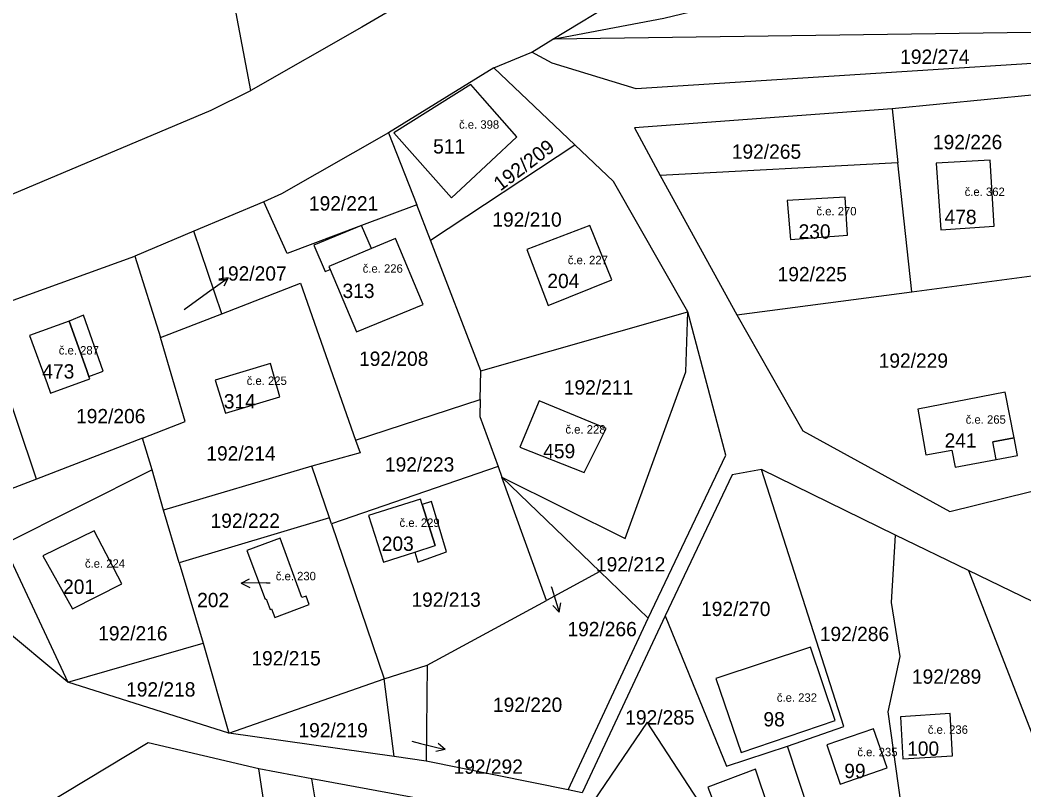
# Model space of a CAD drawing. Extents: x -887272 to -880188, y -1026687 to -1021896.
# Drawn here: x -882201.9 to -882082.9, y -1024103.2 to -1024011.9 of the extents above; entities that cross this region are included whole.
import ezdxf

# ---------------------------------------------------------------- set-up
doc = ezdxf.new("R2010")
doc.units = 0
for name, color, linetype in [('Definiční body', 7, 'Continuous'), ('Hranice parcel', 7, 'Continuous'), ('Parcelní čísla', 7, 'Continuous'), ('Polygon budovy', 7, 'Continuous'), ('Pop  PČ popisy', 7, 'Continuous'), ('Vnitřní kresba', 7, 'Continuous')]:
    doc.layers.add(name, color=color, linetype=linetype)

msp = doc.modelspace()

# ---------------------------------------------------------------- linework, layer by layer
at = {"layer": 'Hranice parcel'}
for p, q in [((-882138.72, -1024014.17), (-882123.98, -1024005.14)), ((-882141.19, -1024015.69), (-882138.72, -1024014.17)), ((-882145.71, -1024017.54), (-882141.19, -1024015.69)), ((-882145.71, -1024017.54), (-882158.18, -1024025.27)), ((-882136.1, -1024026.69), (-882145.71, -1024017.54)), ((-882081.54, -1024020.75), (-882098.51, -1024022.43)), ((-882098.51, -1024022.43), (-882097.82, -1024028.81)), ((-882158.18, -1024025.27), (-882154.84, -1024033.81)), ((-882153.2, -1024037.99), (-882136.1, -1024026.69)), ((-882097.82, -1024028.81), (-882125.97, -1024030.31)), ((-882096.15, -1024044.11), (-882097.82, -1024028.81)), ((-882125.97, -1024030.31), (-882116.91, -1024046.86)), ((-882172.96, -1024033.47), (-882181.25, -1024036.95)), ((-882170.21, -1024039.58), (-882172.96, -1024033.47)), ((-882153.2, -1024037.99), (-882154.84, -1024033.81)), ((-882181.25, -1024036.95), (-882188.26, -1024039.89)), ((-882177.94, -1024046.73), (-882181.25, -1024036.95)), ((-882147.26, -1024053.51), (-882153.2, -1024037.99)), ((-882206.58, -1024046.52), (-882188.26, -1024039.89)), ((-882188.26, -1024039.89), (-882185.22, -1024049.56)), ((-882096.15, -1024044.11), (-882078.8, -1024041.81)), ((-882116.91, -1024046.86), (-882096.15, -1024044.11)), ((-882199.93, -1024066.33), (-882206.58, -1024046.52)), ((-882185.22, -1024049.56), (-882177.94, -1024046.73)), ((-882147.26, -1024053.51), (-882122.72, -1024046.51)), ((-882147.32, -1024056.9), (-882147.26, -1024053.51)), ((-882162.09, -1024061.72), (-882147.32, -1024056.9)), ((-882187.35, -1024061.47), (-882199.93, -1024066.33)), ((-882186.22, -1024065.24), (-882187.35, -1024061.47)), ((-882184.87, -1024070.04), (-882186.22, -1024065.24)), ((-882167.27, -1024064.79), (-882184.87, -1024070.04)), ((-882165.18, -1024070.94), (-882167.27, -1024064.79)), ((-882145.21, -1024064.85), (-882164.94, -1024071.65)), ((-882145.21, -1024064.85), (-882144.76, -1024066.09)), ((-882098.08, -1024072.99), (-882113.98, -1024065.19)), ((-882199.93, -1024066.33), (-882217.07, -1024073.03)), ((-882144.76, -1024066.09), (-882133.16, -1024077.29)), ((-882139.48, -1024080.73), (-882144.76, -1024066.09)), ((-882183, -1024076.28), (-882184.87, -1024070.04)), ((-882165.18, -1024070.94), (-882183, -1024076.28)), ((-882164.94, -1024071.65), (-882165.18, -1024070.94)), ((-882164.94, -1024071.65), (-882158.69, -1024090.04)), ((-882089.45, -1024077.18), (-882098.08, -1024072.99)), ((-882196.2, -1024090.44), (-882217.07, -1024073.03)), ((-882183, -1024076.28), (-882180.16, -1024085.79)), ((-882133.16, -1024077.29), (-882139.48, -1024080.73)), ((-882133.16, -1024077.29), (-882127.41, -1024082.85)), ((-882089.45, -1024077.18), (-882079.4, -1024103.11)), ((-882153.6, -1024088.41), (-882139.48, -1024080.73)), ((-882136.89, -1024103.2), (-882127.41, -1024082.85)), ((-882125.39, -1024082.57), (-882135.22, -1024103.54)), ((-882196.2, -1024090.44), (-882180.16, -1024085.79)), ((-882180.16, -1024085.79), (-882177.1, -1024096.46)), ((-882158.69, -1024090.04), (-882153.6, -1024088.41)), ((-882153.6, -1024088.41), (-882153.74, -1024099.78)), ((-882177.1, -1024096.46), (-882196.2, -1024090.44)), ((-882177.1, -1024096.46), (-882158.69, -1024090.04)), ((-882157.5, -1024099.25), (-882158.69, -1024090.04)), ((-882157.5, -1024099.25), (-882177.1, -1024096.46)), ((-882106.8, -1024110.48), (-882110.89, -1024098.01)), ((-882153.74, -1024099.78), (-882157.5, -1024099.25)), ((-882136.89, -1024103.2), (-882153.74, -1024099.78)), ((-882171.6, -1024113.68), (-882173.55, -1024100.7)), ((-882167.27, -1024101.87), (-882173.55, -1024100.7)), ((-882162.36, -1024132.25), (-882167.27, -1024101.87)), ((-882135.22, -1024103.54), (-882136.89, -1024103.2))]:
    msp.add_line(p, q, dxfattribs=at)
for points in [[(-882174.49, -1024020.26), (-882208.33, -1023841.98), (-882227.5, -1023772.45), (-882213.17, -1023769.2), (-882180.99, -1023853.37), (-882162.93, -1023941.67)], [(-882138.72, -1024014.17), (-882125.55, -1024011.67), (-882085.96, -1024002.08), (-882063.17, -1024001.87), (-882034.49, -1024011.62), (-882004.55, -1024020.66), (-881996.26, -1024020.9)], [(-882148.29, -1024005.05), (-882161.34, -1024012.72), (-882174.49, -1024020.26)], [(-881966.06, -1024029.4), (-882045.19, -1024012.84), (-882138.72, -1024014.17)], [(-881990.45, -1024031.46), (-882004.32, -1024026.5), (-882043.3, -1024015.89), (-882047.34, -1024014.83), (-882128.82, -1024020.06), (-882138.81, -1024017.01), (-882141.19, -1024015.69)], [(-882340.1, -1024040.68), (-882291.8, -1024041.02), (-882266.44, -1024041.52), (-882231.92, -1024039.84), (-882208.92, -1024035.12), (-882179.22, -1024022.58), (-882174.49, -1024020.26)], [(-882147.04, -1024021.13), (-882148.45, -1024019.53), (-882157.57, -1024025.28), (-882150.72, -1024032.97)], [(-882150.72, -1024032.97), (-882149.08, -1024031.43), (-882142.96, -1024025.76), (-882147.04, -1024021.13)], [(-882098.51, -1024022.43), (-882129.05, -1024024.69), (-882125.97, -1024030.31)], [(-882158.18, -1024025.27), (-882170.87, -1024032.49), (-882172.96, -1024033.47)], [(-882122.72, -1024046.51), (-882131.54, -1024031.03), (-882136.1, -1024026.69)], [(-882086.4, -1024036.35), (-882086.89, -1024028.52), (-882093.28, -1024028.88), (-882092.71, -1024036.76), (-882086.4, -1024036.35)], [(-882103.78, -1024037.42), (-882104.08, -1024032.9), (-882110.92, -1024033.31), (-882110.54, -1024037.9), (-882103.78, -1024037.42)], [(-882154.84, -1024033.81), (-882161.39, -1024036.27), (-882170.21, -1024039.58)], [(-882160.2, -1024038.98), (-882161.39, -1024036.27), (-882167.05, -1024038.59)], [(-882141.79, -1024039.12), (-882139.27, -1024045.73), (-882131.7, -1024042.7), (-882134.31, -1024036.26), (-882141.79, -1024039.12)], [(-882167.05, -1024038.59), (-882165.7, -1024041.71), (-882165.11, -1024041.46), (-882161.99, -1024048.88), (-882154.07, -1024045.61), (-882157.36, -1024037.79), (-882160.2, -1024038.98)], [(-882177.94, -1024046.73), (-882168.62, -1024043.1), (-882162.09, -1024061.72)], [(-882144.76, -1024066.09), (-882130.14, -1024073.37), (-882122.96, -1024053.6), (-882122.72, -1024046.51)], [(-882127.41, -1024082.85), (-882118.21, -1024063.51), (-882122.72, -1024046.51)], [(-882198.66, -1024055), (-882198.26, -1024056.13), (-882193.59, -1024054.46), (-882193.69, -1024054.18), (-882191.99, -1024053.54), (-882194.34, -1024046.88), (-882196.04, -1024047.62), (-882200.75, -1024049.31), (-882198.66, -1024055)], [(-882116.91, -1024046.86), (-882109.08, -1024060.61), (-882091.67, -1024070.17), (-882075.8, -1024066.27)], [(-882187.35, -1024061.47), (-882182.29, -1024059.51), (-882185.22, -1024049.56)], [(-882172.16, -1024052.64), (-882178.74, -1024054.62), (-882177.51, -1024058.53), (-882171.05, -1024056.59), (-882172.16, -1024052.64)], [(-882091.02, -1024064.92), (-882086.18, -1024064.01), (-882083.62, -1024063.53), (-882084.03, -1024061.44), (-882085.09, -1024056.03), (-882095.44, -1024058.05), (-882094.51, -1024063.45), (-882091.4, -1024062.91), (-882091.02, -1024064.92)], [(-882147.32, -1024056.9), (-882147.35, -1024058.92), (-882145.21, -1024064.85)], [(-882132.4, -1024060.34), (-882140.32, -1024057.06), (-882142.64, -1024062.56), (-882134.98, -1024065.56), (-882132.4, -1024060.34)], [(-882162.09, -1024061.72), (-882161.56, -1024063.23), (-882167.27, -1024064.79)], [(-882186.22, -1024065.24), (-882203.83, -1024074.1), (-882196.2, -1024090.44)], [(-882113.98, -1024065.19), (-882117.47, -1024065.82), (-882125.39, -1024082.57)], [(-882110.89, -1024098.01), (-882104.21, -1024095.67), (-882113.98, -1024065.19)], [(-882154.4, -1024068.72), (-882160.55, -1024070.67), (-882158.8, -1024076.18), (-882155.08, -1024075), (-882154.7, -1024076.19), (-882151.32, -1024074.97), (-882153.11, -1024068.99), (-882154.2, -1024069.34), (-882154.4, -1024068.72)], [(-882189.78, -1024078.76), (-882193.08, -1024072.46), (-882199.16, -1024075.44), (-882195.66, -1024081.74), (-882189.78, -1024078.76)], [(-882097.11, -1024107.19), (-882098.95, -1024093.95), (-882097.56, -1024087.36), (-882098.57, -1024080.99), (-882098.08, -1024072.99)], [(-882171.68, -1024082.77), (-882167.58, -1024081.22), (-882167.94, -1024080.21), (-882168.46, -1024080.4), (-882171.04, -1024073.33), (-882174.98, -1024074.82), (-882172.81, -1024080.57), (-882172.7, -1024080.53), (-882172.22, -1024081.79), (-882172.07, -1024081.73), (-882171.68, -1024082.77)], [(-882060.37, -1024098.33), (-882059.72, -1024094.32), (-882061.57, -1024090.71), (-882089.45, -1024077.18)], [(-882125.39, -1024082.57), (-882118.13, -1024100.39), (-882110.89, -1024098.01)], [(-882119.38, -1024089.98), (-882116.4, -1024098.76), (-882105.23, -1024094.97), (-882108.18, -1024086.28), (-882119.38, -1024089.98)], [(-882091.34, -1024099.18), (-882091.62, -1024094.14), (-882097.51, -1024094.52), (-882097.21, -1024099.52), (-882091.34, -1024099.18)], [(-882115.87, -1024113.05), (-882127.53, -1024095.15), (-882133.96, -1024104.67), (-882136.92, -1024107.16)], [(-882104.64, -1024102.51), (-882099.09, -1024100.58), (-882100.71, -1024095.94), (-882106.24, -1024097.84), (-882104.64, -1024102.51)], [(-882173.55, -1024100.7), (-882186.69, -1024097.6), (-882198.92, -1024105.01)], [(-882120.33, -1024102.86), (-882118.57, -1024107.51), (-882113.1, -1024105.46), (-882114.69, -1024100.73), (-882120.33, -1024102.86)], [(-882146.33, -1024121.21), (-882152.94, -1024104.55), (-882167.27, -1024101.87)]]:
    msp.add_lwpolyline(points, dxfattribs=at)
at = {"layer": 'Polygon budovy'}
for points in [[(-882147.04, -1024021.13), (-882148.45, -1024019.53), (-882157.57, -1024025.28), (-882150.72, -1024032.97), (-882149.08, -1024031.43), (-882142.96, -1024025.76)], [(-882093.28, -1024028.88), (-882092.71, -1024036.76), (-882086.4, -1024036.35), (-882086.89, -1024028.52)], [(-882104.08, -1024032.9), (-882110.92, -1024033.31), (-882110.54, -1024037.9), (-882103.78, -1024037.42)], [(-882139.27, -1024045.73), (-882131.7, -1024042.7), (-882134.31, -1024036.26), (-882141.79, -1024039.12)], [(-882157.36, -1024037.79), (-882160.2, -1024038.98), (-882165.26, -1024041.11), (-882165.11, -1024041.46), (-882161.99, -1024048.88), (-882154.07, -1024045.61)], [(-882196.04, -1024047.62), (-882200.75, -1024049.31), (-882198.66, -1024055), (-882198.26, -1024056.13), (-882193.59, -1024054.46), (-882193.69, -1024054.18), (-882193.98, -1024053.35)], [(-882178.74, -1024054.62), (-882177.51, -1024058.53), (-882171.05, -1024056.59), (-882172.16, -1024052.64)], [(-882084.03, -1024061.44), (-882085.09, -1024056.03), (-882095.44, -1024058.05), (-882094.51, -1024063.45), (-882091.4, -1024062.91), (-882091.02, -1024064.92), (-882086.18, -1024064.01), (-882086.57, -1024061.93)], [(-882140.32, -1024057.06), (-882142.64, -1024062.56), (-882134.98, -1024065.56), (-882132.4, -1024060.34)], [(-882158.8, -1024076.18), (-882155.08, -1024075), (-882152.65, -1024074.23), (-882154.2, -1024069.34), (-882154.4, -1024068.72), (-882160.55, -1024070.67)], [(-882193.08, -1024072.46), (-882199.16, -1024075.44), (-882195.66, -1024081.74), (-882189.78, -1024078.76)], [(-882171.04, -1024073.33), (-882174.98, -1024074.82), (-882172.81, -1024080.57), (-882172.7, -1024080.53), (-882172.22, -1024081.79), (-882172.07, -1024081.73), (-882171.68, -1024082.77), (-882167.58, -1024081.22), (-882167.94, -1024080.21), (-882168.46, -1024080.4)], [(-882116.4, -1024098.76), (-882105.23, -1024094.97), (-882108.18, -1024086.28), (-882119.38, -1024089.98)], [(-882091.62, -1024094.14), (-882097.51, -1024094.52), (-882097.21, -1024099.52), (-882091.34, -1024099.18)], [(-882106.24, -1024097.84), (-882104.64, -1024102.51), (-882099.09, -1024100.58), (-882100.71, -1024095.94)], [(-882120.33, -1024102.86), (-882118.57, -1024107.51), (-882113.1, -1024105.46), (-882114.69, -1024100.73)]]:
    msp.add_lwpolyline(points, close=True, dxfattribs=at)
at = {"layer": 'Pop  PČ popisy'}
for p, q in [((-882179.63, -1024044.21), (-882177.2, -1024042.45)), ((-882177.2, -1024042.45), (-882178.31, -1024042.63)), ((-882177.2, -1024042.45), (-882177.72, -1024043.44)), ((-882182.42, -1024046.22), (-882179.63, -1024044.21)), ((-882175.64, -1024078.69), (-882174.65, -1024078.17)), ((-882172.64, -1024078.64), (-882175.64, -1024078.69)), ((-882175.64, -1024078.69), (-882174.63, -1024079.18)), ((-882172.64, -1024078.64), (-882172.22, -1024078.64)), ((-882138.89, -1024079.08), (-882138.84, -1024079.26)), ((-882138.84, -1024079.26), (-882137.96, -1024082.13)), ((-882137.96, -1024082.13), (-882138.73, -1024081.32)), ((-882137.96, -1024082.13), (-882137.78, -1024081.03)), ((-882155.43, -1024097.42), (-882154.38, -1024097.69)), ((-882154.38, -1024097.69), (-882151.47, -1024098.42)), ((-882151.47, -1024098.42), (-882152.32, -1024097.69)), ((-882151.47, -1024098.42), (-882152.56, -1024098.66))]:
    msp.add_line(p, q, dxfattribs=at)
at = {"layer": 'Vnitřní kresba'}
for p, q in [((-882160.2, -1024038.98), (-882165.26, -1024041.11)), ((-882165.26, -1024041.11), (-882165.11, -1024041.46)), ((-882196.04, -1024047.62), (-882193.98, -1024053.35)), ((-882193.98, -1024053.35), (-882193.69, -1024054.18)), ((-882084.03, -1024061.44), (-882086.57, -1024061.93)), ((-882086.18, -1024064.01), (-882086.57, -1024061.93)), ((-882154.2, -1024069.34), (-882152.65, -1024074.23)), ((-882155.08, -1024075), (-882152.65, -1024074.23))]:
    msp.add_line(p, q, dxfattribs=at)

# ---------------------------------------------------------------- texts
at = {"layer": 'Definiční body'}
for s, p in [('č.e. 398', (-882149.83, -1024024.78)), ('č.e. 362', (-882089.9, -1024032.76)), ('č.e. 270', (-882107.47, -1024035.06)), ('č.e. 226', (-882161.25, -1024041.86)), ('č.e. 227', (-882136.94, -1024040.85)), ('č.e. 287', (-882197.27, -1024051.56)), ('č.e. 225', (-882175, -1024055.17)), ('č.e. 265', (-882089.78, -1024059.77)), ('č.e. 228', (-882137.22, -1024060.94)), ('č.e. 229', (-882156.88, -1024072.01)), ('č.e. 224', (-882194.17, -1024076.85)), ('č.e. 230', (-882171.55, -1024078.34)), ('č.e. 232', (-882112.16, -1024092.75)), ('č.e. 236', (-882094.27, -1024096.55)), ('č.e. 235', (-882102.62, -1024099.21))]:
    msp.add_text(s, height=1, dxfattribs=at).set_placement(p)
at = {"layer": 'Parcelní čísla'}
for s, p in [('192/274', (-882097.54, -1024017.09)), ('192/226', (-882093.66, -1024027.21)), ('511', (-882152.9, -1024027.72)), ('192/265', (-882117.5, -1024028.34)), ('192/221', (-882167.62, -1024034.48)), ('192/210', (-882145.88, -1024036.4)), ('478', (-882092.28, -1024036.09)), ('230', (-882109.58, -1024037.82)), ('192/207', (-882178.48, -1024042.8)), ('204', (-882139.36, -1024043.68)), ('192/225', (-882112.07, -1024042.88)), ('313', (-882163.64, -1024044.86)), ('192/208', (-882161.68, -1024052.91)), ('192/229', (-882100.09, -1024053.13)), ('473', (-882199.22, -1024054.41)), ('192/211', (-882137.41, -1024056.31)), ('314', (-882177.71, -1024057.96)), ('192/206', (-882195.22, -1024059.72)), ('241', (-882092.28, -1024062.61)), ('459', (-882139.85, -1024063.87)), ('192/214', (-882179.78, -1024064.14)), ('192/223', (-882158.61, -1024065.45)), ('192/222', (-882179.28, -1024072.12)), ('203', (-882158.99, -1024074.85)), ('192/212', (-882133.6, -1024077.29)), ('201', (-882196.76, -1024079.95)), ('202', (-882180.87, -1024081.53)), ('192/213', (-882155.47, -1024081.48)), ('192/270', (-882121.14, -1024082.58)), ('192/216', (-882192.6, -1024085.48)), ('192/266', (-882136.98, -1024084.98)), ('192/286', (-882107.07, -1024085.55)), ('192/215', (-882174.44, -1024088.44)), ('192/289', (-882096.15, -1024090.61)), ('192/218', (-882189.29, -1024092.13)), ('192/220', (-882145.81, -1024093.95)), ('192/285', (-882130.13, -1024095.45)), ('98', (-882113.75, -1024095.67)), ('192/219', (-882168.86, -1024096.97)), ('100', (-882096.72, -1024099.15)), ('192/292', (-882150.48, -1024101.29)), ('99', (-882104.17, -1024101.8))]:
    msp.add_text(s, height=1.7, dxfattribs=at).set_placement(p)
msp.add_text('192/209', height=1.7, rotation=37, dxfattribs=at).set_placement((-882144.92, -1024032.24))

doc.saveas('drawing.dxf')
